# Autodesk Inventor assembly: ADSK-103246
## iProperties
Shininess: 0.0
Created: 2000-12
Part Number: ADSK-103246
Document SubType Name: Assembly
Designer: gao
Stock Number: ADSK-103246
Density: 0.0
Volumn: 0.0
Area: 0.0
PropertySet Name: Model Information
Control State: 0
Master: False
Checked Out: False
Author: gao
